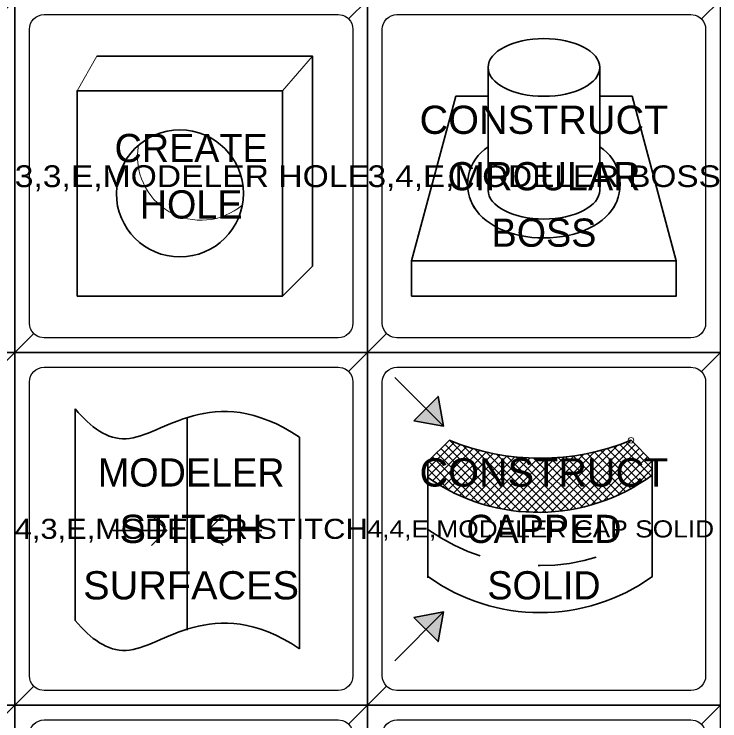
# Model space of a CAD drawing. Extents: x 95909.2 to 95923.3, y 90965 to 90971.2.
# Drawn here: x 95910.986 to 95912.186, y 90968.734 to 90969.936 of the extents above; entities that cross this region are included whole.
import ezdxf
from ezdxf.enums import TextEntityAlignment as Align

# ---------------------------------------------------------------- set-up
doc = ezdxf.new("R2010")
doc.units = 0
doc.header["$LTSCALE"] = 0.019
doc.header["$PDMODE"] = 32
doc.header["$PDSIZE"] = 0.0095
doc.linetypes.add('MEDIUM_DASHED', pattern=[4.5, 3, -1.5])
for name, color, linetype, lineweight in [('1', 7, 'Continuous', 25), ('2', 7, 'Continuous', 25), ('3', 7, 'Continuous', 25), ('4', 7, 'Continuous', 25), ('6', 7, 'Continuous', 13)]:
    doc.layers.add(name, color=color, linetype=linetype, lineweight=lineweight)
doc.layers.add('5', color=7, linetype='Continuous')
doc.layers.add('63', color=7, linetype='Continuous')

msp = doc.modelspace()

# ---------------------------------------------------------------- hatches: boundary and pattern name
at = {"layer": '6'}
for points in [[(95911.6657, 90969.2443), (95911.7161, 90969.2351), (95911.7068, 90969.2856)], [(95911.6657, 90968.9096), (95911.7161, 90968.919), (95911.7068, 90968.8685)]]:
    msp.add_hatch(color=256, dxfattribs=at).paths.add_polyline_path(points)

# ---------------------------------------------------------------- linework, layer by layer
at = {"layer": '1'}
for points in [[(95910.3868, 90969.3603), (95910.9868, 90969.3603), (95910.9868, 90969.9603), (95910.3868, 90969.9603)], [(95910.9868, 90969.3603), (95911.5868, 90969.3603), (95911.5868, 90969.9603), (95910.9868, 90969.9603)], [(95911.5868, 90969.3603), (95912.1868, 90969.3603), (95912.1868, 90969.9603), (95911.5868, 90969.9603)], [(95910.3868, 90968.7603), (95910.9868, 90968.7603), (95910.9868, 90969.3603), (95910.3868, 90969.3603)], [(95910.9868, 90968.7603), (95911.5868, 90968.7603), (95911.5868, 90969.3603), (95910.9868, 90969.3603)], [(95911.5868, 90968.7603), (95912.1868, 90968.7603), (95912.1868, 90969.3603), (95911.5868, 90969.3603)], [(95910.3868, 90968.1603), (95910.9868, 90968.1603), (95910.9868, 90968.7603), (95910.3868, 90968.7603)], [(95910.9868, 90968.1603), (95911.5868, 90968.1603), (95911.5868, 90968.7603), (95910.9868, 90968.7603)], [(95911.5868, 90968.1603), (95912.1868, 90968.1603), (95912.1868, 90968.7603), (95911.5868, 90968.7603)]]:
    msp.add_lwpolyline(points, close=True, dxfattribs=at)
at = {"layer": '2'}
for points in [[(95910.3868, 90969.3603), (95910.9868, 90969.3603), (95910.9868, 90969.9603), (95910.3868, 90969.9603)], [(95910.9868, 90969.3603), (95911.5868, 90969.3603), (95911.5868, 90969.9603), (95910.9868, 90969.9603)], [(95911.5868, 90969.3603), (95912.1868, 90969.3603), (95912.1868, 90969.9603), (95911.5868, 90969.9603)], [(95910.3868, 90968.7603), (95910.9868, 90968.7603), (95910.9868, 90969.3603), (95910.3868, 90969.3603)], [(95910.9868, 90968.7603), (95911.5868, 90968.7603), (95911.5868, 90969.3603), (95910.9868, 90969.3603)], [(95911.5868, 90968.7603), (95912.1868, 90968.7603), (95912.1868, 90969.3603), (95911.5868, 90969.3603)], [(95910.3868, 90968.1603), (95910.9868, 90968.1603), (95910.9868, 90968.7603), (95910.3868, 90968.7603)], [(95910.9868, 90968.1603), (95911.5868, 90968.1603), (95911.5868, 90968.7603), (95910.9868, 90968.7603)], [(95911.5868, 90968.1603), (95912.1868, 90968.1603), (95912.1868, 90968.7603), (95911.5868, 90968.7603)]]:
    msp.add_lwpolyline(points, close=True, dxfattribs=at)
at = {"layer": '3'}
for points in [[(95911.5868, 90969.9603), (95910.9868, 90969.9603), (95910.9868, 90969.3603), (95911.0191, 90969.3926), (95911.016, 90969.3964), (95911.0137, 90969.4007), (95911.0123, 90969.4054), (95911.0118, 90969.4103), (95911.0118, 90969.9103), (95911.0123, 90969.9152), (95911.0137, 90969.9199), (95911.016, 90969.9242), (95911.0191, 90969.928), (95911.0191, 90969.928), (95911.0229, 90969.9311), (95911.0272, 90969.9334), (95911.0319, 90969.9348), (95911.0368, 90969.9353), (95911.5368, 90969.9353), (95911.5441, 90969.9342), (95911.5486, 90969.9323), (95911.5527, 90969.9296), (95911.5545, 90969.928)], [(95912.1868, 90969.9603), (95911.5868, 90969.9603), (95911.5868, 90969.3603), (95911.6191, 90969.3926), (95911.616, 90969.3964), (95911.6137, 90969.4007), (95911.6123, 90969.4054), (95911.6118, 90969.4103), (95911.6118, 90969.9103), (95911.6123, 90969.9152), (95911.6137, 90969.9199), (95911.616, 90969.9242), (95911.6191, 90969.928), (95911.6191, 90969.928), (95911.6229, 90969.9311), (95911.6272, 90969.9334), (95911.6319, 90969.9348), (95911.6368, 90969.9353), (95912.1368, 90969.9353), (95912.1441, 90969.9342), (95912.1486, 90969.9323), (95912.1527, 90969.9296), (95912.1545, 90969.928)], [(95910.9868, 90969.3603), (95910.3868, 90969.3603), (95910.3868, 90968.7603), (95910.4191, 90968.7926), (95910.416, 90968.7964), (95910.4137, 90968.8007), (95910.4123, 90968.8054), (95910.4118, 90968.8103), (95910.4118, 90969.3103), (95910.4123, 90969.3152), (95910.4137, 90969.3199), (95910.416, 90969.3242), (95910.4191, 90969.328), (95910.4191, 90969.328), (95910.4229, 90969.3311), (95910.4272, 90969.3334), (95910.4319, 90969.3348), (95910.4368, 90969.3353), (95910.9368, 90969.3353), (95910.9441, 90969.3342), (95910.9486, 90969.3323), (95910.9527, 90969.3296), (95910.9545, 90969.328)], [(95911.5868, 90969.3603), (95910.9868, 90969.3603), (95910.9868, 90968.7603), (95911.0191, 90968.7926), (95911.016, 90968.7964), (95911.0137, 90968.8007), (95911.0123, 90968.8054), (95911.0118, 90968.8103), (95911.0118, 90969.3103), (95911.0123, 90969.3152), (95911.0137, 90969.3199), (95911.016, 90969.3242), (95911.0191, 90969.328), (95911.0191, 90969.328), (95911.0229, 90969.3311), (95911.0272, 90969.3334), (95911.0319, 90969.3348), (95911.0368, 90969.3353), (95911.5368, 90969.3353), (95911.5441, 90969.3342), (95911.5486, 90969.3323), (95911.5527, 90969.3296), (95911.5545, 90969.328)], [(95912.1868, 90969.3603), (95911.5868, 90969.3603), (95911.5868, 90968.7603), (95911.6191, 90968.7926), (95911.616, 90968.7964), (95911.6137, 90968.8007), (95911.6123, 90968.8054), (95911.6118, 90968.8103), (95911.6118, 90969.3103), (95911.6123, 90969.3152), (95911.6137, 90969.3199), (95911.616, 90969.3242), (95911.6191, 90969.328), (95911.6191, 90969.328), (95911.6229, 90969.3311), (95911.6272, 90969.3334), (95911.6319, 90969.3348), (95911.6368, 90969.3353), (95912.1368, 90969.3353), (95912.1441, 90969.3342), (95912.1486, 90969.3323), (95912.1527, 90969.3296), (95912.1545, 90969.328)], [(95910.9868, 90968.7603), (95910.3868, 90968.7603), (95910.3868, 90968.1603), (95910.4191, 90968.1926), (95910.416, 90968.1964), (95910.4137, 90968.2007), (95910.4123, 90968.2054), (95910.4118, 90968.2103), (95910.4118, 90968.7103), (95910.4123, 90968.7152), (95910.4137, 90968.7199), (95910.416, 90968.7242), (95910.4191, 90968.728), (95910.4191, 90968.728), (95910.4229, 90968.7311), (95910.4272, 90968.7334), (95910.4319, 90968.7348), (95910.4368, 90968.7353), (95910.9368, 90968.7353), (95910.9441, 90968.7342), (95910.9486, 90968.7323), (95910.9527, 90968.7296), (95910.9545, 90968.728)], [(95911.5868, 90968.7603), (95910.9868, 90968.7603), (95910.9868, 90968.1603), (95911.0191, 90968.1926), (95911.016, 90968.1964), (95911.0137, 90968.2007), (95911.0123, 90968.2054), (95911.0118, 90968.2103), (95911.0118, 90968.7103), (95911.0123, 90968.7152), (95911.0137, 90968.7199), (95911.016, 90968.7242), (95911.0191, 90968.728), (95911.0191, 90968.728), (95911.0229, 90968.7311), (95911.0272, 90968.7334), (95911.0319, 90968.7348), (95911.0368, 90968.7353), (95911.5368, 90968.7353), (95911.5441, 90968.7342), (95911.5486, 90968.7323), (95911.5527, 90968.7296), (95911.5545, 90968.728)], [(95912.1868, 90968.7603), (95911.5868, 90968.7603), (95911.5868, 90968.1603), (95911.6191, 90968.1926), (95911.616, 90968.1964), (95911.6137, 90968.2007), (95911.6123, 90968.2054), (95911.6118, 90968.2103), (95911.6118, 90968.7103), (95911.6123, 90968.7152), (95911.6137, 90968.7199), (95911.616, 90968.7242), (95911.6191, 90968.728), (95911.6191, 90968.728), (95911.6229, 90968.7311), (95911.6272, 90968.7334), (95911.6319, 90968.7348), (95911.6368, 90968.7353), (95912.1368, 90968.7353), (95912.1441, 90968.7342), (95912.1486, 90968.7323), (95912.1527, 90968.7296), (95912.1545, 90968.728)]]:
    msp.add_lwpolyline(points, close=True, dxfattribs=at)
at = {"layer": '4'}
for points in [[(95910.3868, 90969.3603), (95910.9868, 90969.3603), (95910.9868, 90969.9603), (95910.9545, 90969.928), (95910.9576, 90969.9242), (95910.9599, 90969.9199), (95910.9613, 90969.9152), (95910.9618, 90969.9103), (95910.9618, 90969.4103), (95910.9613, 90969.4054), (95910.9599, 90969.4007), (95910.9576, 90969.3964), (95910.9545, 90969.3926), (95910.9545, 90969.3926), (95910.9507, 90969.3895), (95910.9464, 90969.3872), (95910.9417, 90969.3858), (95910.9368, 90969.3853), (95910.4368, 90969.3853), (95910.4295, 90969.3864), (95910.425, 90969.3883), (95910.4209, 90969.391), (95910.4191, 90969.3926)], [(95910.9868, 90969.3603), (95911.5868, 90969.3603), (95911.5868, 90969.9603), (95911.5545, 90969.928), (95911.5576, 90969.9242), (95911.5599, 90969.9199), (95911.5613, 90969.9152), (95911.5618, 90969.9103), (95911.5618, 90969.4103), (95911.5613, 90969.4054), (95911.5599, 90969.4007), (95911.5576, 90969.3964), (95911.5545, 90969.3926), (95911.5545, 90969.3926), (95911.5507, 90969.3895), (95911.5464, 90969.3872), (95911.5417, 90969.3858), (95911.5368, 90969.3853), (95911.0368, 90969.3853), (95911.0295, 90969.3864), (95911.025, 90969.3883), (95911.0209, 90969.391), (95911.0191, 90969.3926)], [(95911.5868, 90969.3603), (95912.1868, 90969.3603), (95912.1868, 90969.9603), (95912.1545, 90969.928), (95912.1576, 90969.9242), (95912.1599, 90969.9199), (95912.1613, 90969.9152), (95912.1618, 90969.9103), (95912.1618, 90969.4103), (95912.1613, 90969.4054), (95912.1599, 90969.4007), (95912.1576, 90969.3964), (95912.1545, 90969.3926), (95912.1545, 90969.3926), (95912.1507, 90969.3895), (95912.1464, 90969.3872), (95912.1417, 90969.3858), (95912.1368, 90969.3853), (95911.6368, 90969.3853), (95911.6295, 90969.3864), (95911.625, 90969.3883), (95911.6209, 90969.391), (95911.6191, 90969.3926)], [(95910.3868, 90968.7603), (95910.9868, 90968.7603), (95910.9868, 90969.3603), (95910.9545, 90969.328), (95910.9576, 90969.3242), (95910.9599, 90969.3199), (95910.9613, 90969.3152), (95910.9618, 90969.3103), (95910.9618, 90968.8103), (95910.9613, 90968.8054), (95910.9599, 90968.8007), (95910.9576, 90968.7964), (95910.9545, 90968.7926), (95910.9545, 90968.7926), (95910.9507, 90968.7895), (95910.9464, 90968.7872), (95910.9417, 90968.7858), (95910.9368, 90968.7853), (95910.4368, 90968.7853), (95910.4295, 90968.7864), (95910.425, 90968.7883), (95910.4209, 90968.791), (95910.4191, 90968.7926)], [(95910.9868, 90968.7603), (95911.5868, 90968.7603), (95911.5868, 90969.3603), (95911.5545, 90969.328), (95911.5576, 90969.3242), (95911.5599, 90969.3199), (95911.5613, 90969.3152), (95911.5618, 90969.3103), (95911.5618, 90968.8103), (95911.5613, 90968.8054), (95911.5599, 90968.8007), (95911.5576, 90968.7964), (95911.5545, 90968.7926), (95911.5545, 90968.7926), (95911.5507, 90968.7895), (95911.5464, 90968.7872), (95911.5417, 90968.7858), (95911.5368, 90968.7853), (95911.0368, 90968.7853), (95911.0295, 90968.7864), (95911.025, 90968.7883), (95911.0209, 90968.791), (95911.0191, 90968.7926)], [(95911.5868, 90968.7603), (95912.1868, 90968.7603), (95912.1868, 90969.3603), (95912.1545, 90969.328), (95912.1576, 90969.3242), (95912.1599, 90969.3199), (95912.1613, 90969.3152), (95912.1618, 90969.3103), (95912.1618, 90968.8103), (95912.1613, 90968.8054), (95912.1599, 90968.8007), (95912.1576, 90968.7964), (95912.1545, 90968.7926), (95912.1545, 90968.7926), (95912.1507, 90968.7895), (95912.1464, 90968.7872), (95912.1417, 90968.7858), (95912.1368, 90968.7853), (95911.6368, 90968.7853), (95911.6295, 90968.7864), (95911.625, 90968.7883), (95911.6209, 90968.791), (95911.6191, 90968.7926)], [(95910.3868, 90968.1603), (95910.9868, 90968.1603), (95910.9868, 90968.7603), (95910.9545, 90968.728), (95910.9576, 90968.7242), (95910.9599, 90968.7199), (95910.9613, 90968.7152), (95910.9618, 90968.7103), (95910.9618, 90968.2103), (95910.9613, 90968.2054), (95910.9599, 90968.2007), (95910.9576, 90968.1964), (95910.9545, 90968.1926), (95910.9545, 90968.1926), (95910.9507, 90968.1895), (95910.9464, 90968.1872), (95910.9417, 90968.1858), (95910.9368, 90968.1853), (95910.4368, 90968.1853), (95910.4295, 90968.1864), (95910.425, 90968.1883), (95910.4209, 90968.191), (95910.4191, 90968.1926)], [(95910.9868, 90968.1603), (95911.5868, 90968.1603), (95911.5868, 90968.7603), (95911.5545, 90968.728), (95911.5576, 90968.7242), (95911.5599, 90968.7199), (95911.5613, 90968.7152), (95911.5618, 90968.7103), (95911.5618, 90968.2103), (95911.5613, 90968.2054), (95911.5599, 90968.2007), (95911.5576, 90968.1964), (95911.5545, 90968.1926), (95911.5545, 90968.1926), (95911.5507, 90968.1895), (95911.5464, 90968.1872), (95911.5417, 90968.1858), (95911.5368, 90968.1853), (95911.0368, 90968.1853), (95911.0295, 90968.1864), (95911.025, 90968.1883), (95911.0209, 90968.191), (95911.0191, 90968.1926)], [(95911.5868, 90968.1603), (95912.1868, 90968.1603), (95912.1868, 90968.7603), (95912.1545, 90968.728), (95912.1576, 90968.7242), (95912.1599, 90968.7199), (95912.1613, 90968.7152), (95912.1618, 90968.7103), (95912.1618, 90968.2103), (95912.1613, 90968.2054), (95912.1599, 90968.2007), (95912.1576, 90968.1964), (95912.1545, 90968.1926), (95912.1545, 90968.1926), (95912.1507, 90968.1895), (95912.1464, 90968.1872), (95912.1417, 90968.1858), (95912.1368, 90968.1853), (95911.6368, 90968.1853), (95911.6295, 90968.1864), (95911.625, 90968.1883), (95911.6209, 90968.191), (95911.6191, 90968.1926)]]:
    msp.add_lwpolyline(points, close=True, dxfattribs=at)
at = {"layer": '6'}
for p, q in [((95911.0929, 90969.8057), (95911.1266, 90969.8643)), ((95911.4423, 90969.8057), (95911.4933, 90969.8643)), ((95911.4423, 90969.4563), (95911.4933, 90969.5072)), ((95911.7259, 90969.211), (95911.847, 90969.0899)), ((95911.9144, 90969.0906), (95912.0349, 90969.211)), ((95912.0349, 90969.211), (95912.0349, 90969.2111)), ((95911.6895, 90969.1627), (95911.7345, 90969.2076)), ((95911.6896, 90969.1486), (95911.7449, 90969.2039)), ((95911.6975, 90969.1423), (95911.7554, 90969.2002)), ((95911.7188, 90969.2039), (95911.8309, 90969.0917)), ((95911.7484, 90969.2026), (95911.8622, 90969.0888)), ((95911.8989, 90969.0891), (95912.0124, 90969.2026)), ((95911.9309, 90969.0929), (95912.042, 90969.204)), ((95912.0053, 90969.2003), (95912.0607, 90969.1448)), ((95912.0159, 90969.2038), (95912.0691, 90969.1506)), ((95912.0262, 90969.2077), (95912.0711, 90969.1627)), ((95911.7046, 90969.1898), (95911.7956, 90969.0988)), ((95911.7061, 90969.1368), (95911.7662, 90969.1969)), ((95911.7117, 90969.1968), (95911.8139, 90969.0946)), ((95911.715, 90969.1315), (95911.7773, 90969.1939)), ((95911.7241, 90969.1265), (95911.7886, 90969.191)), ((95911.7335, 90969.1217), (95911.8003, 90969.1885)), ((95911.7431, 90969.1172), (95911.8122, 90969.1864)), ((95911.7691, 90969.1961), (95911.8767, 90969.0884)), ((95911.7881, 90969.1911), (95911.8906, 90969.0887)), ((95911.806, 90969.1874), (95911.9039, 90969.0894)), ((95911.8563, 90969.089), (95911.9548, 90969.1875)), ((95911.8699, 90969.0885), (95911.9727, 90969.1912)), ((95911.8841, 90969.0885), (95911.9918, 90969.1962)), ((95911.9484, 90969.0963), (95912.049, 90969.1969)), ((95911.9485, 90969.1863), (95912.0157, 90969.1192)), ((95911.9604, 90969.1886), (95912.0252, 90969.1238)), ((95911.9673, 90969.101), (95912.0561, 90969.1898)), ((95911.972, 90969.1911), (95912.0344, 90969.1287)), ((95911.9834, 90969.1938), (95912.0434, 90969.1338)), ((95911.9944, 90969.1969), (95912.0522, 90969.1392)), ((95911.6905, 90969.1757), (95911.7532, 90969.1129)), ((95911.6975, 90969.1827), (95911.7758, 90969.1045)), ((95911.753, 90969.113), (95911.8244, 90969.1844)), ((95911.7631, 90969.109), (95911.837, 90969.1829)), ((95911.7736, 90969.1053), (95911.85, 90969.1817)), ((95911.7844, 90969.1019), (95911.8634, 90969.1809)), ((95911.7954, 90969.0988), (95911.8771, 90969.1805)), ((95911.8068, 90969.096), (95911.8914, 90969.1807)), ((95911.8186, 90969.0937), (95911.9063, 90969.1814)), ((95911.8229, 90969.1846), (95911.9167, 90969.0908)), ((95911.8308, 90969.0918), (95911.9217, 90969.1827)), ((95911.839, 90969.1826), (95911.9291, 90969.0926)), ((95911.8433, 90969.0902), (95911.9379, 90969.1847)), ((95911.8544, 90969.1814), (95911.9411, 90969.0947)), ((95911.8692, 90969.1808), (95911.9527, 90969.0972)), ((95911.8835, 90969.1806), (95911.964, 90969.1001)), ((95911.8973, 90969.1809), (95911.9749, 90969.1034)), ((95911.9107, 90969.1817), (95911.9855, 90969.1069)), ((95911.9236, 90969.1829), (95911.9959, 90969.1107)), ((95911.9362, 90969.1845), (95912.0059, 90969.1148)), ((95911.9883, 90969.1079), (95912.0631, 90969.1827)), ((95912.012, 90969.1174), (95912.0702, 90969.1756)), ((95911.6895, 90969.1624), (95911.7269, 90969.125)), ((95912.0411, 90969.1324), (95912.0711, 90969.1624)), ((95911.6896, 90969.1482), (95911.6916, 90969.1462))]:
    msp.add_line(p, q, dxfattribs=at)
at = {"layer": '6', "lineweight": 35}
for p, q in [((95911.7918, 90969.8453), (95911.7918, 90969.6365)), ((95911.9816, 90969.8453), (95911.9816, 90969.6365)), ((95911.6617, 90969.5163), (95911.7368, 90969.7963)), ((95911.7368, 90969.7963), (95911.7918, 90969.7963)), ((95911.9816, 90969.7963), (95912.0367, 90969.7963)), ((95912.1117, 90969.5163), (95912.0367, 90969.7963)), ((95911.6331, 90969.318), (95911.7161, 90969.2351)), ((95911.0895, 90969.2643), (95911.0895, 90968.9043)), ((95911.2803, 90969.248), (95911.2803, 90968.888)), ((95911.4711, 90969.2163), (95911.4711, 90968.8563)), ((95911.6895, 90969.1747), (95911.7259, 90969.2111)), ((95912.0349, 90969.2111), (95912.0711, 90969.1747)), ((95911.6895, 90968.9792), (95911.6895, 90969.1747)), ((95912.0711, 90969.1747), (95912.0711, 90968.9792)), ((95911.2453, 90969.0577), (95911.2196, 90969.032)), ((95911.3154, 90969.0577), (95911.3411, 90969.032)), ((95911.6331, 90968.8359), (95911.7161, 90968.919))]:
    msp.add_line(p, q, dxfattribs=at)
at = {"layer": '6', "linetype": 'MEDIUM_DASHED', "lineweight": 35}
msp.add_line((95911.6895, 90968.9772), (95911.6895, 90968.9792), dxfattribs=at)
at = {"layer": '6', "lineweight": 35}
for points in [[(95911.4933, 90969.5072), (95911.4933, 90969.8643), (95911.1266, 90969.8643)], [(95911.7259, 90969.211), (95911.6895, 90969.1747), (95911.6896, 90969.1476)], [(95912.0711, 90969.152), (95912.0711, 90969.1747), (95912.0349, 90969.2111), (95912.0349, 90969.211)], [(95911.1535, 90969.0577), (95911.2453, 90969.0577), (95911.2196, 90969.0835)], [(95911.4073, 90969.0577), (95911.3154, 90969.0577), (95911.3411, 90969.0835)]]:
    msp.add_lwpolyline(points, dxfattribs=at)
for points in [[(95911.0929, 90969.4563), (95911.4423, 90969.4563), (95911.4423, 90969.8057), (95911.0929, 90969.8057)], [(95911.6617, 90969.4563), (95912.1117, 90969.4563), (95912.1117, 90969.5163), (95911.6617, 90969.5163)], [(95911.6657, 90969.2443), (95911.7161, 90969.2351), (95911.7068, 90969.2856)], [(95911.6657, 90968.9096), (95911.7161, 90968.919), (95911.7068, 90968.8685)]]:
    msp.add_lwpolyline(points, close=True, dxfattribs=at)
msp.add_circle((95911.26762, 90969.63103), 0.108, dxfattribs=at)
at = {"layer": '6'}
msp.add_arc((95911.30362, 90969.69338), 0.108, 169.46843, 310.52482, dxfattribs=at)
at = {"layer": '6', "lineweight": 35}
for centre, radius, start, end in [((95911.83262, 90969.64661), 0.07557, 122.66326, 214.32931), ((95911.9409, 90969.64661), 0.07557, 325.67069, 57.33674), ((95911.88036, 90969.58705), 0.40655, 247.66353, 292.33647), ((95911.87724, 90969.4153), 0.32695, 234.97768, 306.36881), ((95911.88036, 90969.24472), 0.32695, 234.30728, 305.69272)]:
    msp.add_arc(centre, radius, start, end, dxfattribs=at)
at = {"layer": '6', "linetype": 'MEDIUM_DASHED', "lineweight": 35}
msp.add_arc((95911.88036, 90969.32473), 0.32695, 234.30728, 305.69272, dxfattribs=at)
at = {"layer": '6', "lineweight": 35}
msp.add_ellipse((95911.88676, 90969.84531), major_axis=(0.09492, 0), ratio=0.517312, dxfattribs=at)
for major_axis, ratio, start_param, end_param in [((0.09492, 0), 0.517312, 3.1416618, 6.2831028), ((0.12718, 0), 0.639741, 3.4186888, 6.0101757)]:
    msp.add_ellipse((95911.88676, 90969.63657), major_axis=major_axis, ratio=ratio, start_param=start_param, end_param=end_param, dxfattribs=at)
for points in [[(95911.0895, 90969.2643), (95911.1162, 90969.233), (95911.1727, 90969.1907), (95911.2781, 90969.2643), (95911.3964, 90969.2664), (95911.4711, 90969.2163)], [(95911.0895, 90968.9043), (95911.1162, 90968.873), (95911.1727, 90968.8307), (95911.2781, 90968.9043), (95911.3964, 90968.9064), (95911.4711, 90968.8563)]]:
    msp.add_open_spline(points, degree=3, dxfattribs=at)
at = {"layer": '6'}
msp.add_point((95912.0349, 90969.211), dxfattribs=at)

# ---------------------------------------------------------------- texts
at = {"layer": '5', "width": 1.05}
for s, p in [('CONSTRUCT', (95911.8868, 90969.7323)), ('CONSTRUCT', (95911.8868, 90969.1323)), ('STITCH', (95911.2868, 90969.0363)), ('SURFACES', (95911.28675, 90968.9403))]:
    msp.add_text(s, height=0.048, dxfattribs=at).set_placement(p, align=Align.CENTER)
at = {"layer": '5'}
for s, p in [('CREATE', (95911.28675, 90969.6843)), ('CIRCULAR', (95911.88685, 90969.6363)), ('HOLE', (95911.2868, 90969.5883)), ('BOSS', (95911.8868, 90969.5403)), ('MODELER', (95911.28685, 90969.1323)), ('CAPPED', (95911.8868, 90969.0363)), ('SOLID', (95911.8868, 90968.9403))]:
    msp.add_text(s, height=0.048, dxfattribs=at).set_placement(p, align=Align.CENTER)
at = {"layer": '63', "width": 1.15}
for s, height, p in [('3,3,E,MODELER HOLE', 0.0372, (95910.9868, 90969.6417)), ('3,4,E,MODELER BOSS', 0.0368, (95911.5868, 90969.6419)), ('4,3,E,MODELER STITCH', 0.0341, (95910.9868, 90969.0433)), ('4,4,E,MODELER CAP SOLID', 0.0291, (95911.5868, 90969.0457))]:
    msp.add_text(s, height=height, dxfattribs=at).set_placement(p)

doc.saveas('drawing.dxf')
